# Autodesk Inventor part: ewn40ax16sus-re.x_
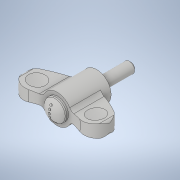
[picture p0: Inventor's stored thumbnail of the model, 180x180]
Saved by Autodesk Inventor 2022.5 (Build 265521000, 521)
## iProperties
Created: 2021-08
Part Number: ewn40ax16sus-re.x_
Material: 一般
Document SubType Name: Modeling
Designer: ImaoCorp
Density: 1 g/cm^3
Appearance: 既定
Sending System: SOLIDWORKS 2019-2019304
MC: AMD64
MC_MODEL: Intel64 Family 6 Model 60 Stepping 3, GenuineIntel
OS: Windows_NT
FRU: Parasolid Version 31.0, build 290,  9- 1-2019
FORMAT: text
GUISE: transmit
KEY: ewn40ax16sus-re
FILE: ewn40ax16sus-re.x_t
DATE: Wed Aug 11 15:03:15 2021
Author: ImaoCorp
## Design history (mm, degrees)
feature "Base1"
node "ソリッド1"
